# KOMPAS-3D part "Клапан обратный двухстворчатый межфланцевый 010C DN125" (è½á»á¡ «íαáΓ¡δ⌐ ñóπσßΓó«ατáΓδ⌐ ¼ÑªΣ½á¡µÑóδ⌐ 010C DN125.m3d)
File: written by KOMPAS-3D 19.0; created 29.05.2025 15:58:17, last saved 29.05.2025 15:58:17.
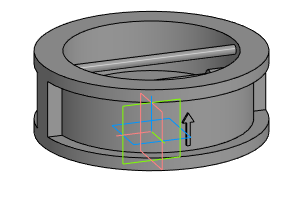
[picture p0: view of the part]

Document properties: Полное имя файла: E:\Dendor Работа Сачек\3D для проекитирвщиков\5.2 Тип 010C, 010C.Y Клапан обратный двухстворчатый межфланцевый\stp_Клапан обратный двухстворчатый межфланцевый 010C\Клапан обратный двухстворчатый межфланцевый 010C DN125.m3d

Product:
- Part/product: Клапан обратный двухстворчатый межфланцевый 010C DN125

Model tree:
1. Операция без истории:1  (labels: Клапан обратный двухстворчатый межфланцевый 010C DN125)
